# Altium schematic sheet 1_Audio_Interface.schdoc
size 429 x 307 mm; Symbol: Drawing-Symbol_A4; Device: Drawing-Symbol_A4; @Project Name: Slowpoke_Adapter; @Page Count: 1; @Update Date: 2025-12-10; @Create Date: 2025-12-10; @Schematic Name: Schematic5; @Page No: 1; @Page Name: Audio_Interface; Company: EasyEDA.com; Version: V1.0; Page Size: A4; @Create Time: 09:04:12; @Update Time: 17:06:06; Width: 1655; Height: 1170; Region Start: 1; X Region Count: 6; Y Region Count: 4; Blade Width: 10; Title Block Position: 3; @Board Name: AUDIO_INTERFACE
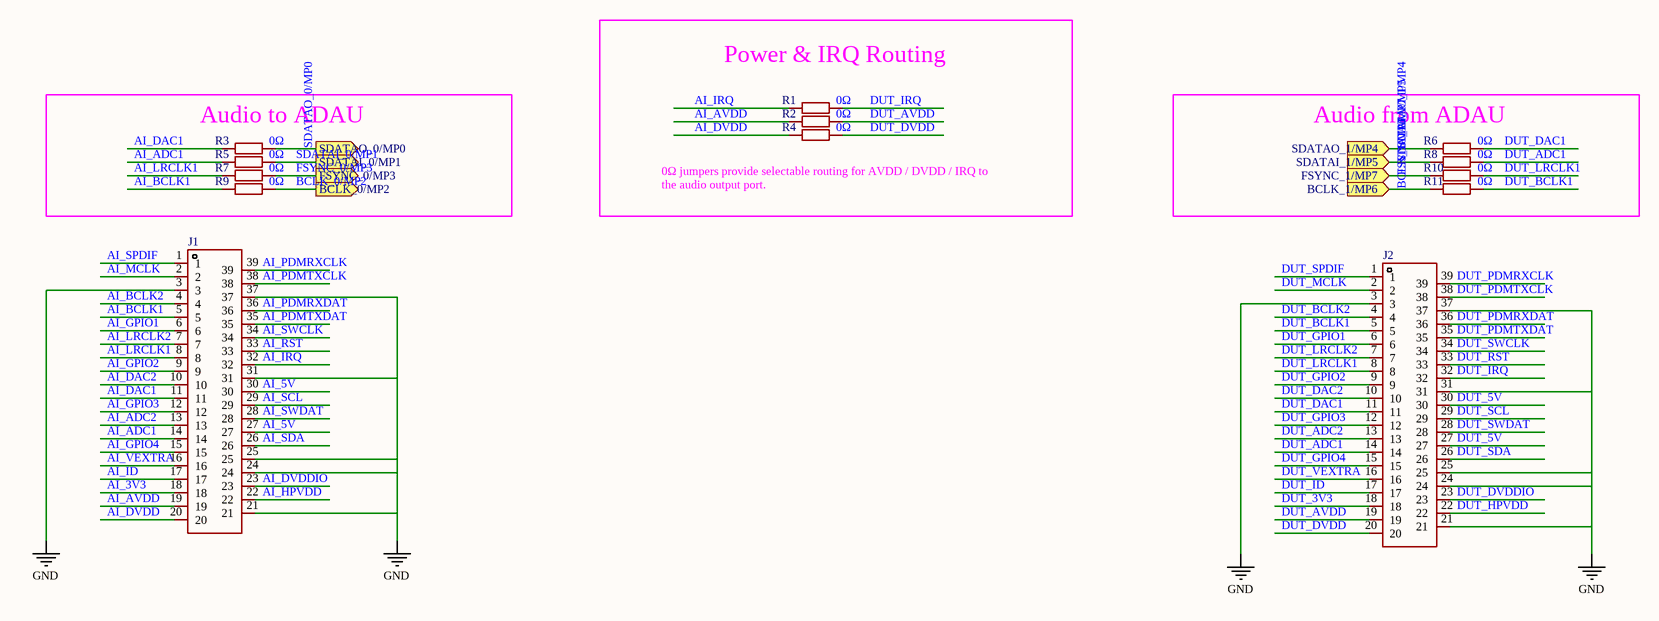
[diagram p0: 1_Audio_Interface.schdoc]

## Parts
J1  TSW-113-08-G-T-RA  [HDR-TH_TSW-113-08-G-T-RA]  (value not drawn)
J2  TSW-113-08-G-T-RA  [HDR-TH_TSW-113-08-G-T-RA]  (value not drawn)
R1  0Ω  [R0603]
R2  0Ω  [R0603]
R3  0Ω  [R0603]
R4  0Ω  [R0603]
R5  0Ω  [R0603]
R6  0Ω  [R0603]
R7  0Ω  [R0603]
R8  0Ω  [R0603]
R9  0Ω  [R0603]
R10  0Ω  [R0603]
R11  0Ω  [R0603]

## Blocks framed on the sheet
Power & IRQ Routing: R1 R2 R4
Audio to ADAU: R3 R5 R7 R9
Audio from ADAU: R6 R8 R10 R11

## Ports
BCLK_0/MP2 (out), BCLK_1/MP6 (in), FSYNC_0/MP3 (out), FSYNC_1/MP7 (in), SDATAI_0/MP1 (out), SDATAI_1/MP5 (in), SDATAO_0/MP0 (out), SDATAO_1/MP4 (in)

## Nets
GND: J1.3 J1.21 J1.24 J1.25 J1.31 J1.37 J2.3 J2.21 J2.24 J2.25 J2.31 J2.37
AI_3V3: J1.18
AI_5V: J1.27 J1.30
AI_ADC1: J1.14 R5.1
AI_ADC2: J1.13
AI_AVDD: J1.19 R2.1
AI_BCLK1: J1.5 R9.1
AI_BCLK2: J1.4
AI_DAC1: J1.11 R3.1
AI_DAC2: J1.10
AI_DVDD: J1.20 R4.1
AI_DVDDIO: J1.23
AI_GPIO1: J1.6
AI_GPIO2: J1.9
AI_GPIO3: J1.12
AI_GPIO4: J1.15
AI_HPVDD: J1.22
AI_ID: J1.17
AI_IRQ: J1.32 R1.1
AI_LRCLK1: J1.8 R7.1
AI_LRCLK2: J1.7
AI_MCLK: J1.2
AI_PDMRXCLK: J1.39
AI_PDMRXDAT: J1.36
AI_PDMTXCLK: J1.38
AI_PDMTXDAT: J1.35
AI_RST: J1.33
AI_SCL: J1.29
AI_SDA: J1.26
AI_SPDIF: J1.1
AI_SWCLK: J1.34
AI_SWDAT: J1.28
AI_VEXTRA: J1.16
BCLK_0/MP2: R9.2 ; port BCLK_0/MP2
BCLK_1/MP6: R11.1 ; port BCLK_1/MP6
DUT_3V3: J2.18
DUT_5V: J2.27 J2.30
DUT_ADC1: J2.14 R8.2
DUT_ADC2: J2.13
DUT_AVDD: J2.19 R2.2
DUT_BCLK1: J2.5 R11.2
DUT_BCLK2: J2.4
DUT_DAC1: J2.11 R6.2
DUT_DAC2: J2.10
DUT_DVDD: J2.20 R4.2
DUT_DVDDIO: J2.23
DUT_GPIO1: J2.6
DUT_GPIO2: J2.9
DUT_GPIO3: J2.12
DUT_GPIO4: J2.15
DUT_HPVDD: J2.22
DUT_ID: J2.17
DUT_IRQ: J2.32 R1.2
DUT_LRCLK1: J2.8 R10.2
DUT_LRCLK2: J2.7
DUT_MCLK: J2.2
DUT_PDMRXCLK: J2.39
DUT_PDMRXDAT: J2.36
DUT_PDMTXCLK: J2.38
DUT_PDMTXDAT: J2.35
DUT_RST: J2.33
DUT_SCL: J2.29
DUT_SDA: J2.26
DUT_SPDIF: J2.1
DUT_SWCLK: J2.34
DUT_SWDAT: J2.28
DUT_VEXTRA: J2.16
FSYNC_0/MP3: R7.2 ; port FSYNC_0/MP3
FSYNC_1/MP7: R10.1 ; port FSYNC_1/MP7
SDATAI_0/MP1: R5.2 ; port SDATAI_0/MP1
SDATAI_1/MP5: R8.1 ; port SDATAI_1/MP5
SDATAO_0/MP0: R3.2 ; port SDATAO_0/MP0
SDATAO_1/MP4: R6.1 ; port SDATAO_1/MP4

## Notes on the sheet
- 0Ω jumpers provide selectable routing for AVDD / DVDD / IRQ to
  the audio output port.

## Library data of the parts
J1 J2 = TSW-113-08-G-T-RA: Manufacturer: SAMTEC; Add into BOM: yes; Pitch: 2.54mm
R1-R11 = 0603WAF0000T5E: Manufacturer: UNI-ROYAL(厚声); Add into BOM: yes; Tolerance: ±1%; Power(Watts): 100mW; Voltage-Supply(Max): 75V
